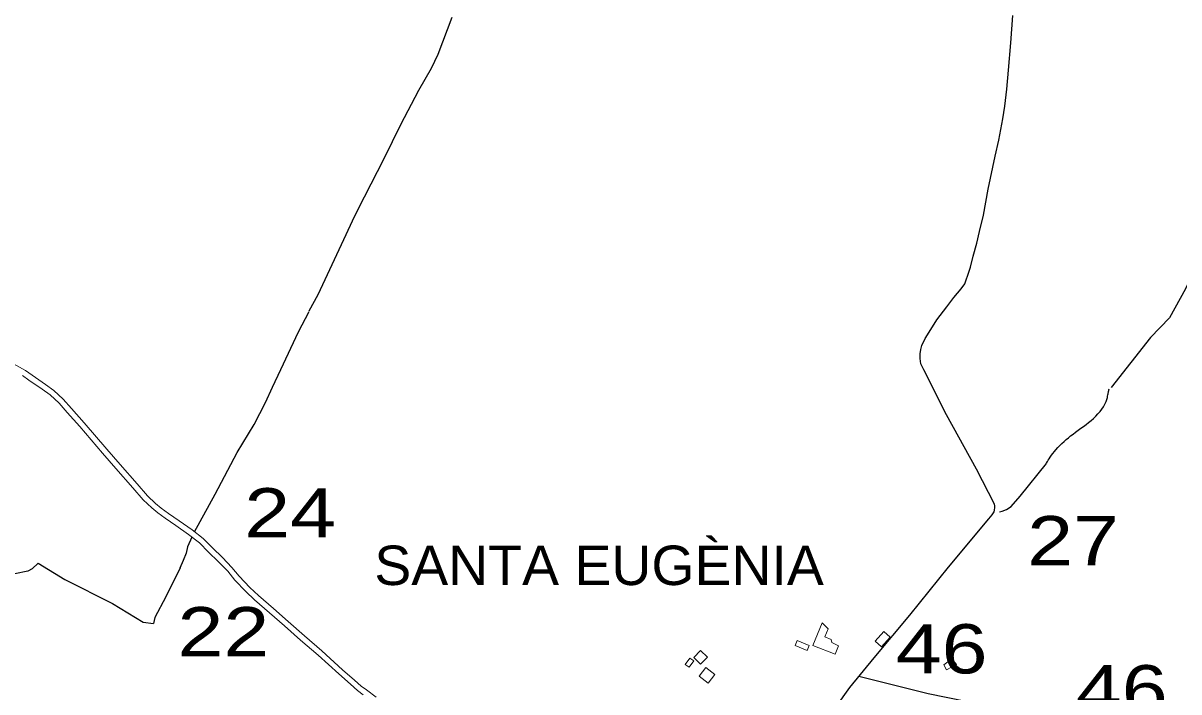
# Model space of a CAD drawing. Extents: x 476989 to 498418, y 4381813 to 4416555.
# Drawn here: x 485599 to 486771, y 4386458 to 4387137 of the extents above; entities that cross this region are included whole.
import ezdxf
from ezdxf.enums import TextEntityAlignment as Align

# ---------------------------------------------------------------- set-up
doc = ezdxf.new("R2010")
doc.units = 0
doc.header["$LTSCALE"] = 20
for name, color, linetype, lineweight in [('13', 7, 'Continuous', 13), ('36', 7, 'Continuous', 13), ('47', 7, 'Continuous', 13), ('6', 7, 'Continuous', 25)]:
    doc.layers.add(name, color=color, linetype=linetype, lineweight=lineweight)
doc.layers.add('7', color=7, linetype='Continuous')

msp = doc.modelspace()

# ---------------------------------------------------------------- linework, layer by layer
at = {"layer": '36'}
for points in [[(485574.47, 4386799.34), (485601.49, 4386784.39), (485608.29, 4386779.54), (485621.78, 4386770.31), (485630.2, 4386764.12), (485639.68, 4386755.33), (485648.17, 4386745.82), (485660.98, 4386731.48), (485684.06, 4386704.54), (485697.45, 4386688.93), (485714.72, 4386669.33), (485725.09, 4386657.39), (485733.36, 4386649.47), (485739.11, 4386644.68), (485746.54, 4386639.47), (485757.24, 4386631.89), (485770.36, 4386622.7), (485781.69, 4386613.91), (485791.03, 4386604.44), (485801.13, 4386594.74), (485810.85, 4386584.65), (485818.25, 4386575.74), (485829.07, 4386564.32), (485837.71, 4386556.08), (485852.8, 4386542.97), (485867.86, 4386529.7), (485884.28, 4386515.38), (485901.98, 4386500.14), (485923.03, 4386480.92), (485935.07, 4386470.44), (485941.64, 4386464.26), (485947.14, 4386460.32), (485956.97, 4386452.87)], [(485598.37, 4386779.45), (485604.95, 4386774.75), (485618.4, 4386765.55), (485626.48, 4386759.62), (485635.51, 4386751.24), (485643.81, 4386741.94), (485656.59, 4386727.64), (485679.63, 4386700.74), (485693.05, 4386685.1), (485710.33, 4386665.49), (485720.86, 4386653.36), (485729.47, 4386645.11), (485735.56, 4386640.04), (485743.18, 4386634.7), (485753.88, 4386627.12), (485766.9, 4386618), (485777.81, 4386609.54), (485786.93, 4386600.29), (485797.01, 4386590.61), (485806.5, 4386580.76), (485813.89, 4386571.86), (485824.94, 4386560.19), (485833.78, 4386551.77), (485848.96, 4386538.58), (485864.01, 4386525.31), (485880.46, 4386510.97), (485898.1, 4386495.78), (485919.15, 4386476.56), (485931.15, 4386466.11), (485937.93, 4386459.74), (485943.93, 4386455.44)]]:
    msp.add_lwpolyline(points, dxfattribs=at)
at = {"layer": '47'}
for points in [[(486409.02, 4386528.55), (486399.69, 4386505.35), (486422.22, 4386496.55), (486425.65, 4386505.21), (486418.79, 4386508.38), (486418.31, 4386511.39), (486411.67, 4386514.18), (486415.31, 4386522.39)], [(486478.07, 4386513.91), (486469.4, 4386504.07), (486462.93, 4386509.77), (486471.6, 4386519.61)], [(486393.91, 4386500.41), (486381.69, 4386505.37), (486383.78, 4386510.53), (486396, 4386505.57)], [(486274.94, 4386492.66), (486270.38, 4386486.19), (486274.29, 4386483.44), (486278.85, 4386489.91)], [(486279, 4386493.2), (486285.91, 4386486.53), (486292.82, 4386493.68), (486285.91, 4386500.35)], [(486532.52, 4386485.82), (486540.48, 4386491.78), (486545.21, 4386486.16), (486541.1, 4386482.39), (486539.61, 4386483.16), (486535, 4386480.9)], [(486291.24, 4386482.97), (486300.3, 4386475.94), (486293.56, 4386467.25), (486284.5, 4386474.28)]]:
    msp.add_lwpolyline(points, close=True, dxfattribs=at)
at = {"layer": '6'}
for points in [[(485889.1, 4386844.91), (485898.22, 4386861.52), (485924.32, 4386917.39), (485935.38, 4386941.3), (485945.1, 4386960.49), (485965.17, 4386999.61), (485982.1, 4387034.09), (486000.35, 4387068.9), (486013.22, 4387091.19), (486019.79, 4387105.48), (486034.18, 4387142.83)], [(486422.93, 4386442.97), (486437.29, 4386462.9), (486461.79, 4386492.9), (486497.8, 4386536.1), (486537.07, 4386584.84), (486578.11, 4386634.12), (486581.4, 4386637.95), (486583.45, 4386640.96), (486583.84, 4386642.66), (486584.19, 4386645.4), (486584.16, 4386647.06), (486583.81, 4386648.94), (486565.38, 4386684.49), (486535.01, 4386739.36), (486512.11, 4386785.07), (486509.15, 4386791.37), (486508.47, 4386796.71), (486508.54, 4386801.18), (486508.95, 4386805.87), (486509.96, 4386809.7), (486513.59, 4386817), (486517.47, 4386823.37), (486525.21, 4386835.78), (486535.57, 4386849.15), (486542.53, 4386858.46), (486550.1, 4386867.13), (486553.64, 4386872.31), (486554.7, 4386875.55), (486557.07, 4386882.23), (486559.57, 4386889.33), (486562.24, 4386900.36), (486565.72, 4386913.63), (486568.44, 4386925.51), (486572.63, 4386941.95), (486577.49, 4386968.25), (486584.52, 4387002.01), (486588.12, 4387018.18), (486592.09, 4387039.77), (486594.27, 4387052.64), (486596.22, 4387069.83), (486597.85, 4387089.12), (486600.42, 4387116.95), (486602.31, 4387144.73)], [(486868.26, 4387136.57), (486811.84, 4387000.91), (486805.15, 4386983.72), (486795.59, 4386928.58), (486789.85, 4386894.19), (486777.42, 4386867.44), (486761.17, 4386837.83), (486742.05, 4386817.76), (486701.89, 4386767.13)], [(485772.9, 4386620.73), (485793.92, 4386659.02), (485816.04, 4386701.22), (485833.41, 4386729.64), (485844.8, 4386751.93), (485852.09, 4386767.68), (485860.52, 4386785.33), (485878.39, 4386823.62), (485889.18, 4386844.24)], [(486589, 4386640.89), (486591.61, 4386641.68), (486595.98, 4386643.36), (486600.66, 4386646.38), (486609.74, 4386656.94), (486636.66, 4386690.23)], [(485770.04, 4386615.49), (485765.93, 4386605.5), (485764.36, 4386599.24), (485761.42, 4386591.8), (485757.89, 4386583.77)], [(485614.42, 4386588.88), (485608.24, 4386583.25), (485603.79, 4386581.02), (485590.67, 4386577.99), (485569.57, 4386574.82), (485555.53, 4386573.67), (485552.14, 4386573.42), (485549.36, 4386573.22), (485546.88, 4386573.26), (485541.5, 4386573.42), (485538.28, 4386574.27), (485529.3, 4386577.31), (485524.93, 4386579.57), (485522.13, 4386581.47), (485519.82, 4386582.6), (485513.12, 4386583.13), (485507.1, 4386583.36), (485502.68, 4386583.42), (485498.06, 4386583.56), (485495.44, 4386583.92), (485492.88, 4386586.05)], [(485614.42, 4386588.88), (485641.39, 4386572.37), (485689.82, 4386547.96), (485720.72, 4386529.08), (485731.35, 4386527.79)], [(485758.23, 4386584.1), (485743.68, 4386554.82), (485732.57, 4386533.82), (485731.35, 4386527.79)], [(486446.35, 4386474.47), (486516.68, 4386456.82), (486574.68, 4386445.04), (486582.92, 4386443.32)]]:
    msp.add_lwpolyline(points, dxfattribs=at)
msp.add_spline([(486636.53, 4386690.49), (486640.14, 4386696.4), (486646.1, 4386704.12), (486663.36, 4386719.93), (486697.87, 4386755.98), (486698.91, 4386760.92), (486699.56, 4386764.06), (486700, 4386765.74)], degree=3, dxfattribs=at)

# ---------------------------------------------------------------- texts
at = {"layer": '13', "width": 1.25}
for s, p in [('24', (485869.79, 4386615.04)), ('27', (486663.45, 4386586.78)), ('22', (485802.15, 4386494.43)), ('46', (486530.23, 4386477.09)), ('46', (486712.75, 4386435.52))]:
    msp.add_text(s, height=50, dxfattribs=at).set_placement(p, align=Align.CENTER)
at = {"layer": '7', "width": 1.05}
msp.add_text('SANTA EUGÈNIA', height=40, dxfattribs=at).set_placement((486182.95, 4386566.79), align=Align.CENTER)

doc.saveas('drawing.dxf')
